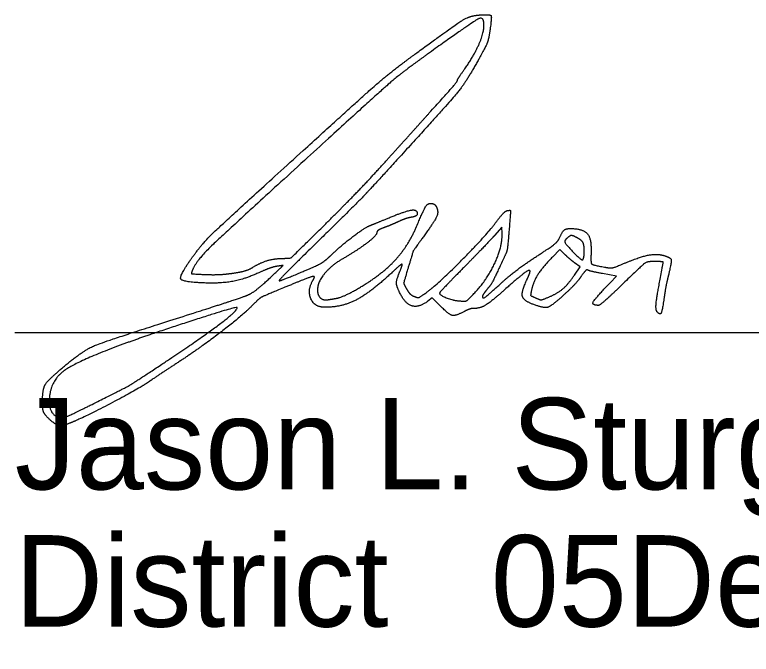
# Model space of a CAD drawing. Extents: x 0 to 34, y 0 to 22.
# Drawn here: x 24.5 to 25.627, y 8.324 to 9.302 of the extents above; entities that cross this region are included whole.
import ezdxf

# ---------------------------------------------------------------- set-up
doc = ezdxf.new("R2010")
doc.units = 0
doc.layers.add('SH_Data', color=7, linetype='Continuous')
doc.layers.add('SH_Text', color=7, linetype='Continuous')

msp = doc.modelspace()

# ---------------------------------------------------------------- linework, layer by layer
at = {"layer": 'SH_Data'}
msp.add_line((24.5, 8.816), (28, 8.816), dxfattribs=at)
for points in [[(25.2455, 8.9679), (25.2451, 8.9772), (25.234, 8.9646)], [(25.3412, 8.9359), (25.334, 8.943), (25.3225, 8.9314)], [(25.3562, 8.9038), (25.3647, 8.9164), (25.3565, 8.9226)], [(25.4109, 8.8922), (25.4206, 8.9022), (25.3991, 8.9062)], [(25.1499, 8.8577), (25.1388, 8.8689), (25.1318, 8.8638)]]:
    msp.add_lwpolyline(points, dxfattribs=at)
for points in [[(25.1132, 9.2426), (25.1743, 9.2875), (25.1964, 9.3008), (25.2112, 9.3019)], [(25.2177, 9.2838), (25.2184, 9.3004), (25.2013, 9.2921), (25.1316, 9.242)], [(25.2112, 9.3019), (25.2274, 9.303), (25.23, 9.2987), (25.2267, 9.277)], [(25.1885, 9.2195), (25.2015, 9.2379), (25.2172, 9.2724), (25.2177, 9.2838)], [(25.2267, 9.277), (25.2248, 9.264), (25.2205, 9.2535), (25.2088, 9.2323)], [(24.9412, 9.0945), (25.0394, 9.1838), (25.0756, 9.215), (25.1132, 9.2426)], [(25.1316, 9.242), (25.0908, 9.2127), (25.0639, 9.1894), (24.9431, 9.0793)], [(25.2088, 9.2323), (25.1907, 9.1996), (25.1668, 9.1702), (25.0914, 9.0875)], [(25.1773, 9.2023), (25.1773, 9.2031), (25.1823, 9.2109), (25.1885, 9.2195)], [(25.1342, 9.1519), (25.1651, 9.1862), (25.1772, 9.2004), (25.1773, 9.2023)], [(25.0691, 9.0797), (25.0911, 9.1041), (25.1203, 9.1366), (25.1342, 9.1519)], [(24.7678, 8.9257), (24.7852, 8.9505), (24.8187, 8.9832), (24.9412, 9.0945)], [(25.0914, 9.0875), (25.039, 9.0301), (25.0228, 9.0134), (24.9381, 8.9301)], [(24.9431, 9.0793), (24.8174, 8.9646), (24.7772, 8.9251), (24.7713, 8.9103)], [(24.9758, 8.9825), (25.0052, 9.0116), (25.0472, 9.0553), (25.0691, 9.0797)], [(25.1136, 8.9759), (25.126, 9.0048), (25.1316, 9.0138), (25.1374, 9.0135)], [(25.0742, 8.9923), (25.0985, 9.0023), (25.116, 9.0045), (25.1157, 8.9975)], [(25.1452, 9.0077), (25.1486, 9.0005), (25.1427, 8.9868), (25.1262, 8.964)], [(25.1374, 9.0135), (25.1402, 9.0134), (25.1437, 9.0108), (25.1452, 9.0077)], [(25.2363, 8.9848), (25.2433, 8.9943), (25.2512, 9.0023), (25.2539, 9.0027)], [(25.2539, 9.0027), (25.2585, 9.0034), (25.2586, 9.0016), (25.2562, 8.9724)], [(25.0438, 8.9799), (25.0475, 8.9813), (25.0612, 8.9869), (25.0742, 8.9923)], [(25.1069, 8.9924), (25.1021, 8.9916), (25.0928, 8.9884), (25.0862, 8.9853)], [(25.1157, 8.9975), (25.1156, 8.9955), (25.1117, 8.9932), (25.1069, 8.9924)], [(24.9114, 8.9295), (24.9221, 8.9297), (24.9239, 8.9312), (24.9758, 8.9825)], [(24.9825, 8.9331), (24.9971, 8.9474), (25.0354, 8.9766), (25.0438, 8.9799)], [(25.0862, 8.9853), (25.0795, 8.9822), (25.0695, 8.9781), (25.064, 8.9762)], [(25.1293, 8.8769), (25.1463, 8.889), (25.2215, 8.9648), (25.2363, 8.9848)], [(25.0538, 8.9686), (25.0536, 8.9642), (25.0233, 8.9412), (24.9996, 8.9275)], [(25.064, 8.9762), (25.0585, 8.9742), (25.0539, 8.9708), (25.0538, 8.9686)], [(25.0587, 8.9057), (25.0776, 8.9203), (25.1047, 8.955), (25.1136, 8.9759)], [(25.2562, 8.9724), (25.254, 8.9461), (25.2524, 8.9386), (25.2457, 8.9245)], [(25.3329, 8.9598), (25.3375, 8.9704), (25.3439, 8.9755), (25.3522, 8.9752)], [(25.3522, 8.9752), (25.3707, 8.9743), (25.3826, 8.9586), (25.3816, 8.936)], [(25.1262, 8.964), (25.1099, 8.9414), (25.1093, 8.9403), (25.1016, 8.9143)], [(25.234, 8.9646), (25.2279, 8.9577), (25.2065, 8.9354), (25.1865, 8.9151)], [(25.2024, 8.8755), (25.2223, 8.8963), (25.2464, 8.9479), (25.2455, 8.9679)], [(25.298, 8.9324), (25.3184, 8.9455), (25.3311, 8.9555), (25.3329, 8.9598)], [(25.3472, 8.9622), (25.3406, 8.9572), (25.3421, 8.9518), (25.3529, 8.9405)], [(25.3587, 8.9618), (25.3529, 8.9646), (25.3504, 8.9646), (25.3472, 8.9622)], [(25.3711, 8.9373), (25.3716, 8.9489), (25.367, 8.958), (25.3587, 8.9618)], [(25.3565, 8.9226), (25.352, 8.926), (25.3451, 8.932), (25.3412, 8.9359)], [(25.3529, 8.9405), (25.3653, 8.9276), (25.3706, 8.9267), (25.3711, 8.9373)], [(25.3816, 8.936), (25.381, 8.9223), (25.3841, 8.9194), (25.4023, 8.916)], [(25.4337, 8.9224), (25.4563, 8.9319), (25.4824, 8.937), (25.4928, 8.9339)], [(24.7862, 8.892), (24.7565, 8.8934), (24.7516, 8.9023), (24.7678, 8.9257)], [(24.8644, 8.9159), (24.8764, 8.9233), (24.8971, 8.9293), (24.9114, 8.9295)], [(24.9381, 8.9301), (24.9191, 8.9114), (24.9039, 8.8957), (24.9044, 8.8952)], [(24.9383, 8.9083), (24.9625, 8.9185), (24.9745, 8.9253), (24.9825, 8.9331)], [(24.9996, 8.9275), (24.9838, 8.9183), (24.9636, 8.8934), (24.9632, 8.8824)], [(25.2457, 8.9245), (25.232, 8.8955), (25.229, 8.8899), (25.2222, 8.8816)], [(25.2434, 8.891), (25.2559, 8.9024), (25.2804, 8.921), (25.298, 8.9324)], [(25.3225, 8.9314), (25.3076, 8.9162), (25.2937, 8.8946), (25.2909, 8.8824)], [(25.4845, 8.9246), (25.4689, 8.9253), (25.4606, 8.92), (25.4285, 8.8888)], [(25.4904, 8.9145), (25.4922, 8.9239), (25.492, 8.9243), (25.4845, 8.9246)], [(25.4928, 8.9339), (25.5035, 8.9307), (25.505, 8.9245), (25.5001, 8.904)], [(24.8341, 8.9069), (24.8461, 8.9086), (24.8587, 8.9124), (24.8644, 8.9159)], [(24.9015, 8.9174), (24.8965, 8.9167), (24.8838, 8.9122), (24.8735, 8.9075)], [(24.8888, 8.8981), (24.9105, 8.9185), (24.9107, 8.9187), (24.9015, 8.9174)], [(25.0923, 8.9207), (25.0915, 8.9207), (25.0833, 8.9136), (25.0739, 8.9049)], [(25.0893, 8.9099), (25.0917, 8.9158), (25.093, 8.9206), (25.0923, 8.9207)], [(25.1016, 8.9143), (25.0949, 8.8918), (25.0949, 8.8913), (25.0994, 8.8828)], [(25.1865, 8.9151), (25.1664, 8.8947), (25.1499, 8.8773), (25.1499, 8.8763)], [(25.3761, 8.9119), (25.3753, 8.9127), (25.371, 8.9083), (25.3666, 8.9021)], [(25.4023, 8.916), (25.4116, 8.9144), (25.4169, 8.9154), (25.4337, 8.9224)], [(25.4828, 8.8475), (25.48, 8.8505), (25.4827, 8.8741), (25.4904, 8.9145)], [(24.7713, 8.9103), (24.7697, 8.9062), (24.7717, 8.9057), (24.7915, 8.9048)], [(24.8735, 8.9075), (24.8512, 8.8974), (24.8136, 8.8907), (24.7862, 8.892)], [(24.7915, 8.9048), (24.8036, 8.9043), (24.8228, 8.9052), (24.8341, 8.9069)], [(24.9044, 8.8952), (24.9048, 8.8947), (24.9201, 8.9006), (24.9383, 8.9083)], [(24.958, 8.9019), (24.9573, 8.9026), (24.9384, 8.8956), (24.916, 8.8863)], [(24.9557, 8.8949), (24.9576, 8.898), (24.9586, 8.9012), (24.958, 8.9019)], [(25.0739, 8.9049), (25.0427, 8.8759), (24.9975, 8.8537), (24.9719, 8.8548)], [(24.9924, 8.8684), (25.0014, 8.8699), (25.0418, 8.8926), (25.0587, 8.9057)], [(25.088, 8.8788), (25.0836, 8.8885), (25.0839, 8.8964), (25.0893, 8.9099)], [(25.2883, 8.9096), (25.2884, 8.9135), (25.2708, 8.9006), (25.2466, 8.879)], [(25.2838, 8.8974), (25.2862, 8.9025), (25.2882, 8.908), (25.2883, 8.9096)], [(25.3168, 8.8702), (25.3305, 8.876), (25.3467, 8.8899), (25.3562, 8.9038)], [(25.3666, 8.9021), (25.3623, 8.8958), (25.3508, 8.8834), (25.3411, 8.8746)], [(25.3991, 8.9062), (25.3872, 8.9084), (25.3769, 8.911), (25.3761, 8.9119)], [(25.5001, 8.904), (25.4976, 8.8941), (25.4946, 8.8782), (25.4933, 8.8688)], [(24.8548, 8.8727), (24.8619, 8.8756), (24.8758, 8.886), (24.8888, 8.8981)], [(24.9719, 8.8548), (24.958, 8.8554), (24.9476, 8.8812), (24.9557, 8.8949)], [(25.2155, 8.872), (25.2153, 8.8671), (25.2234, 8.8727), (25.2434, 8.891)], [(25.2927, 8.8592), (25.2782, 8.8647), (25.2749, 8.8786), (25.2838, 8.8974)], [(25.3926, 8.8575), (25.3823, 8.858), (25.3876, 8.868), (25.4109, 8.8922)], [(24.916, 8.8863), (24.881, 8.872), (24.8733, 8.8677), (24.8628, 8.8569)], [(24.9632, 8.8824), (24.9628, 8.874), (24.9715, 8.865), (24.979, 8.8662)], [(25.1318, 8.8638), (25.1173, 8.8534), (25.0965, 8.8605), (25.088, 8.8788)], [(25.0994, 8.8828), (25.1019, 8.878), (25.107, 8.8729), (25.1108, 8.8714)], [(25.2466, 8.879), (25.2279, 8.8623), (25.2108, 8.8525), (25.201, 8.8528)], [(25.2222, 8.8816), (25.2186, 8.8771), (25.2156, 8.8728), (25.2155, 8.872)], [(25.2909, 8.8824), (25.289, 8.8738), (25.2894, 8.8723), (25.2948, 8.8699)], [(25.4285, 8.8888), (25.4107, 8.8715), (25.3946, 8.8574), (25.3926, 8.8575)], [(24.7786, 8.8475), (24.8139, 8.8587), (24.8481, 8.8701), (24.8548, 8.8727)], [(24.979, 8.8662), (24.9822, 8.8667), (24.9883, 8.8677), (24.9924, 8.8684)], [(25.1108, 8.8714), (25.1165, 8.8691), (25.1194, 8.8699), (25.1293, 8.8769)], [(25.1499, 8.8763), (25.1497, 8.8732), (25.1713, 8.8649), (25.1814, 8.8643)], [(25.1814, 8.8643), (25.1897, 8.8638), (25.1926, 8.8653), (25.2024, 8.8755)], [(25.3411, 8.8746), (25.3215, 8.8566), (25.3096, 8.8528), (25.2927, 8.8592)], [(25.2948, 8.8699), (25.3035, 8.866), (25.3068, 8.866), (25.3168, 8.8702)], [(25.4933, 8.8688), (25.4905, 8.8491), (25.4873, 8.8426), (25.4828, 8.8475)], [(24.8628, 8.8569), (24.8471, 8.8409), (24.7815, 8.7909), (24.7462, 8.7679)], [(25.1869, 8.8478), (25.1739, 8.8409), (25.164, 8.8436), (25.1499, 8.8577)], [(24.5715, 8.7608), (24.6036, 8.7883), (24.6402, 8.8036), (24.7786, 8.8475)], [(24.84, 8.8543), (24.8387, 8.8558), (24.7082, 8.8137), (24.6656, 8.7981)], [(24.7232, 8.7663), (24.7828, 8.8057), (24.843, 8.8511), (24.84, 8.8543)], [(25.201, 8.8528), (25.1986, 8.8529), (25.1922, 8.8506), (25.1869, 8.8478)], [(24.6656, 8.7981), (24.5955, 8.7724), (24.5541, 8.7415), (24.5529, 8.7137)], [(24.6182, 8.7061), (24.6695, 8.7317), (24.6795, 8.7374), (24.7232, 8.7663)], [(24.7462, 8.7679), (24.7313, 8.7582), (24.7119, 8.7453), (24.7032, 8.7393)], [(24.5424, 8.7142), (24.5431, 8.7308), (24.5507, 8.743), (24.5715, 8.7608)], [(24.7032, 8.7393), (24.6884, 8.7292), (24.6022, 8.6842), (24.5846, 8.6775)], [(24.5557, 8.681), (24.5462, 8.6892), (24.5418, 8.7002), (24.5424, 8.7142)], [(24.5529, 8.7137), (24.5523, 8.7006), (24.5624, 8.686), (24.5725, 8.6854)], [(24.5725, 8.6854), (24.5746, 8.6852), (24.5951, 8.6945), (24.6182, 8.7061)], [(24.5846, 8.6775), (24.5734, 8.6732), (24.5634, 8.6744), (24.5557, 8.681)]]:
    msp.add_open_spline(points, degree=2, dxfattribs=at)

# ---------------------------------------------------------------- texts
at = {"layer": 'SH_Text'}
for s, p in [('Jason L. Sturgeon, P.E.', (24.5, 8.576)), ('District       Deputy Director', (24.5, 8.366)), ('              05', (24.5, 8.366))]:
    msp.add_text(s, height=0.14, dxfattribs=at).set_placement(p)

doc.saveas('drawing.dxf')
